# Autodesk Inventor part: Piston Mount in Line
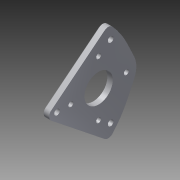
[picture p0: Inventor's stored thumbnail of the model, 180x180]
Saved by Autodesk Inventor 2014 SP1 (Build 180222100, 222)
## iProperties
Created: 2014-08
Part Number: Piston Mount in Line
Material: Aluminum 6061
Document SubType Name: Sheet Metal
Designer: User
Density: 2.71 g/cm^3
Sheet Metal Rule: Default
Appearance: Aluminum - Flat
Author: User
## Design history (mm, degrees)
node "Face1"
  sketch "Sketch1"
    geometry: L1 (-0.653, 21.797)-(-45.382, -22.931); L2 (44.427, -21.977)-(0.653, 21.797); L3 (0, -22.451)-(0, 22.451); L4 (0, 15.5)-(15.5, 0); L5 (15.5, 0)-(0, -15.5); L6 (0, -15.5)-(-15.5, 0); L7 (-15.5, 0)-(0, 15.5); L8 (0.653, 21.797)-(22.451, 0); L9 (22.451, 0)-(0, -22.451); L10 (0, -22.451)-(-22.451, 0); L11 (-22.451, 0)-(-0.653, 21.797); L12 (-19.82, 2.631)-(-19.82, -2.631); L13 (-2.631, -19.82)-(2.631, -19.82); L14 (19.82, -2.631)-(19.82, 2.631); L15 (2.631, 19.82)-(-2.631, 19.82); L16 (-28.063, -5.613)-(0, -33.676); L17 (0, -33.676)-(28.063, -5.613); L18 (-21.328, -12.348)-(0, -22.451); L19 (0, -22.451)-(21.328, -12.348); L20 (28.063, -5.613)-(0, 29.594); L21 (0, 29.594)-(-28.063, -5.613); L22 (-22.451, 0)-(-24.567, -4.821); C1 r 1.38 at (0, 15.5); C2 r 1.38 at (-15.5, 0); C3 r 1.38 at (15.5, 0); C4 r 1.38 at (0, -15.5); C5 r 1.587 at (20.206, -6.735); C6 r 1.587 at (-20.206, -6.735); A1 r 1.587 centre (0, 23.244) between (-0.653, 21.797) and (0.653, 21.797); A2 r 4.762 centre (-20.206, -6.735) between (-24.567, -4.821) and (-23.573, -10.103); 3 further points
    constraints: 45 end point, 8 centre point, 8 point on line, 7 coincident, 4 perpendicular, 4 point on circle, 4 vertical alignment, 2 tangent, 1 collinear, 1 midpoint, 1 symmetric about line, 1 vertical, 33 other
    dimensions: "d0" = 21.9202 distance of L4.start L4.end; "d2" = 4.9149 distance between parallel lines of L7 L11; "d3" = 2.76 diameter of C1; "d4" = 2.76 diameter of C2 (= d3); "d5" = 2.76 diameter of C3 (= d3); "d6" = 2.76 diameter of C4 (= d3); "d8" = 4.32006 distance from line of L6.end L12; "d11" = 360 deg dimension on point (0, 0) L12.start (derived); "d14" = 3.175 diameter of C5 (= d13); "d15" = 4.7625 distance from line of C5.centre L17; "d16" = 3.175 distance from line of L9 C5.centre; "d17" = 6.35 distance from line of L2 C5.centre; "d18" = 9.525 distance of L16.start L18.start; "d26" = 3.175 diameter of A1 (= d14); "d28" = 0.79375 distance of L3.end A1.centre; "d29" = 6.35 distance of L20.end A1.centre
feature "Corner Round1" dims "d20" = 3.175, "d24" = 12.7, "d25" = 50.8
sketch "Sketch2"
  geometry: C1 r 7.938 at (0, 0); 1 further point
  constraints: 1 centre point, 1 coincident
  dimensions: "d21" = 15.875 diameter of C1
cut "Cut1" sketch "Sketch2" dims "d22" = 3.048 (= Thickness), "d23" = 0
body "Solid1"
face "Plate1" dims "Thickness" = 3.048
other parameters: "KFactor" = 4.4, "BendRadius" = 3.048 (= Thickness), "BendReliefWidth" = 3.048 (= Thickness), "BendReliefDepth" = 1.524 (= 0.5 x Thickness), "CornerReliefSize" = 12.192 (= 4 x Thickness), "SeamGap" = 0.00508, "MinimumRemnant" = 6.096 (= 2 x Thickness), "TransitionRadius" = 3.048 (= BendRadius), "JacobiRadiusSize" = 3.048 (= Thickness), "GapSize" = 3.048 (= Thickness), "d13" = 3.175, "d19" = 3.048 (= BendRadius)
